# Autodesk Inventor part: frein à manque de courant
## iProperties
Shininess: 64.0
Length Units: 11269
Angle Units: 11279
Time Units: 11290
Mass Units: 11283
Length Display Precision: 3
Angle Display Precision: 2
Compacted: True
Part Number: frein à manque de courant
Document SubType Name: Modeling
Created: 2004-09
Material: Par défaut
Designer: Laurent
Density: 1 g/cm^3
Density: 0.0
Volumn: 0.0
Area: 0.0
PropertySet Name: Model Information
Control State: 0
Master: False
Checked Out: False
Author: Laurent
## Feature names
1. Extrusion1
2. Extrusion2
3. Extrusion3
4. Extrusion4
5. Perçage1 [Hole]
6. Réseau circulaire1 [Circular Pattern]
